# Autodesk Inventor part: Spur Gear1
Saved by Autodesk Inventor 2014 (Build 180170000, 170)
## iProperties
Created: 2015-07
Part Number: Spur Gear1
Material: Steel
Document SubType Name: Modeling
Designer: Brad Factor
Categories: <?xml version="1.0" encoding="UTF-16"?> <MemberInstance><Categories><FamilyTemplate><FamilyTemplateParameter ValueType="xs:double" Id="1" ObjectReferenceKey="da
Density: 1 g/cm^3
Appearance: Steel
CustomPartVersion: 1
Author: Brad Factor
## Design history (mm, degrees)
sketch "Sketch1"
  geometry: C1 r 9.796 at (0, 0)
  constraints: 1 centre point
  dimensions: "d0" = 19.59189 diameter of C1 (= da_da)
extrude "Extrusion1" new body sketch "Sketch1" distance "d1" = 6.35 (= da_b); taper "d2" = 0 deg
sketch "Sketch2"
  geometry: C1 r 9.796 at (0, 0) reference; C2 r 7.777 at (0, 0)
  constraints: 1 centre point, 1 coincident
  dimensions: "d3" = 15.55483 diameter of C2 (= da_dw)
feature "Pitch Diameter" sketch "Sketch2" dims "d4" = 76.2, "d5" = 0
workplane "Work Plane1"
workplane "Work Plane2"
workplane "Work Plane3"
feature "Spur Gear" dims "da_b" = 6.35, "da_d" = 15.52222, "da_aw" = 84.1375, "da_da" = 19.59189, "da_df" = 13.24467, "da_dw" = 15.55483, angle "da_beta" = 0 deg, "da_lefttooth" = 0, "da_righttooth" = 0
body "Solid1"
body "Srf1"
other parameters: "d6" = 0, "d7" = 2.85599 (computed from da_z), "d9" = 0, "d14" = 0, "d15" = 84.1375 (= da_aw), "d16" = 0, "d17" = 0, "d18" = 0, "d19" = 84.1375 (= da_aw)
